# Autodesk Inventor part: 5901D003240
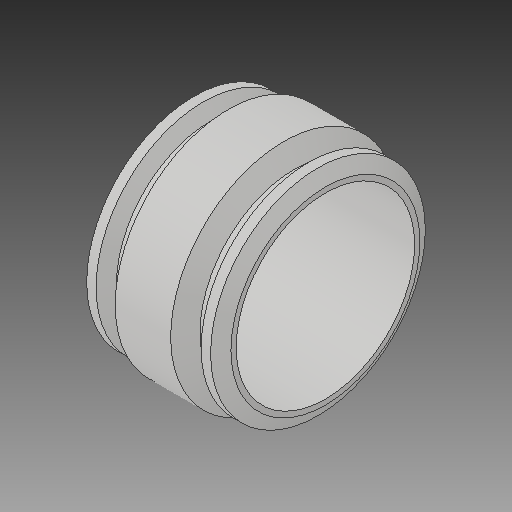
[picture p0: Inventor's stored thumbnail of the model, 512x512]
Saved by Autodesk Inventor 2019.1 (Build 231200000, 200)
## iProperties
Created: 2017-06
Part Number: 5901D003240
Material: Generic
Description: PLASSON COUPLER 24''DIPS
Document SubType Name: Modeling
Designer: KIM
Mass: 96874 g
Surface Area: 34549.7 cm^2
Volume: 96874 cm^3
Density: 1 g/cm^3
Appearance: Default
Author: KIM
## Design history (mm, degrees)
derived "5901D.ipt"
feature "Solid1::5901D.ipt"
tag "TaggingFeature1"
body "Solid1"
other parameters: "d13" = 471.932, "d15" = 235.966, "d16" = 235.966, "d17" = 606.9, "d22" = 729.996, "d23" = 768.858, "d24" = 642.39648, "d25" = 150 deg, "d26" = 188.7728, "d27" = 120 deg, "d29" = 364.998, "d35" = 15, "d39" = 0, "d40" = 4, "d41" = 14, "d42" = 0, "d44" = 82.5881, "d45" = 606.9, "d47" = 0, "d48" = 350.39808, "d49" = 82.5881, "d50" = 60 deg, "d57" = 65.786, "d58" = 82.5881, "d62" = 606.9, "d65" = 364.998, "d67" = 30 deg, "d68" = 120 deg, "d69" = 120 deg, "d70" = 120 deg, "d71" = 120 deg, "d72" = 120 deg, "d73" = 768.858, "d76" = 188.7728, "d77" = 642.39648, "d_" = 606.9, "L_" = 471.932, "L_1" = 235.966, "D_" = 768.858, "A_" = 364.998, "A_1" = 25.4, "d60" = 187.96
